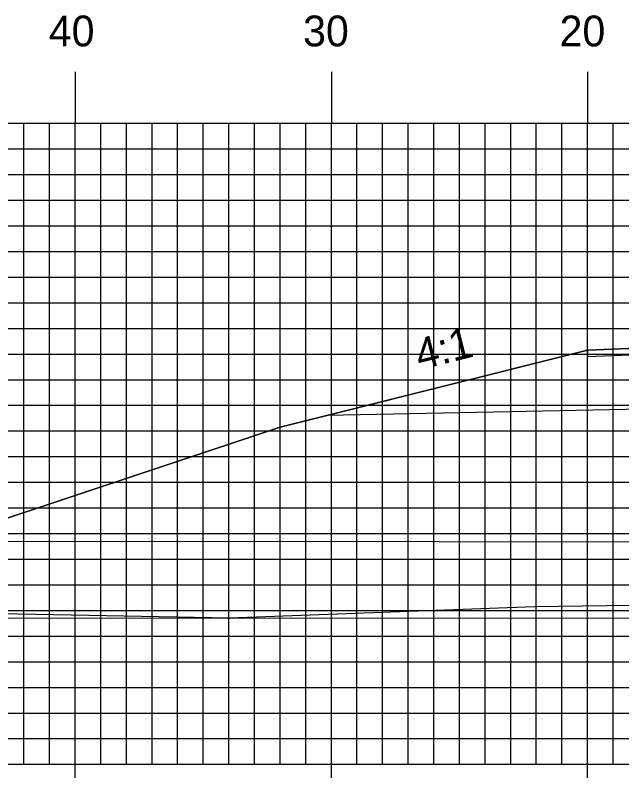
# Model space of a CAD drawing. Extents: x 1819244 to 1819587, y 442591 to 442811.
# Drawn here: x 1819367.32 to 1819391.01, y 442608.41 to 442637.88 of the extents above; entities that cross this region are included whole.
import ezdxf

# ---------------------------------------------------------------- set-up
doc = ezdxf.new("R2010")
doc.units = 0
for name, color, linetype in [('ANNOTATION', 7, 'Continuous'), ('D_Drainage_Culvert', 7, 'Continuous'), ('D_Roadway_Centerline', 7, 'Continuous'), ('D_Roadway_Edge_Shoulder', 7, 'Continuous'), ('D_Roadway_SlopeLines', 7, 'Continuous'), ('D_Roadway_SubGrade', 7, 'Continuous'), ('H_V ANNOTATION', 7, 'Continuous'), ('MAJOR', 7, 'Continuous'), ('MINOR', 7, 'Continuous'), ('S_Roadway_Centerline', 7, 'Continuous')]:
    doc.layers.add(name, color=color, linetype=linetype)

msp = doc.modelspace()

# ---------------------------------------------------------------- linework, layer by layer
at = {"layer": 'D_Drainage_Culvert'}
msp.add_lwpolyline([(1819357.867, 442614.363), (1819357.868, 442617.363), (1819461.868, 442617.321), (1819461.867, 442614.321)], close=True, dxfattribs=at)
at = {"layer": 'D_Roadway_Centerline'}
msp.add_lwpolyline([(1819366.978, 442618.255), (1819377.665, 442621.817), (1819379.491, 442622.273), (1819389.665, 442624.817), (1819397.665, 442625.137), (1819409.665, 442625.377), (1819421.665, 442625.137), (1819429.665, 442624.817), (1819439.839, 442622.273), (1819441.665, 442621.817), (1819452.46, 442618.218)], dxfattribs=at)
at = {"layer": 'D_Roadway_Edge_Shoulder'}
msp.add_lwpolyline([(1819397.665, 442625.137), (1819389.665, 442624.817), (1819389.665, 442624.567), (1819397.665, 442624.887)], close=True, dxfattribs=at)
at = {"layer": 'D_Roadway_SlopeLines'}
msp.add_lwpolyline([(1819389.665, 442624.817), (1819377.665, 442621.817), (1819366.978, 442618.255)], dxfattribs=at)
at = {"layer": 'D_Roadway_SubGrade'}
msp.add_lwpolyline([(1819397.665, 442622.637), (1819379.491, 442622.273), (1819389.665, 442624.817), (1819389.665, 442624.567), (1819397.665, 442624.887), (1819409.665, 442625.127), (1819421.665, 442624.887), (1819429.665, 442624.567), (1819429.665, 442624.817), (1819439.839, 442622.273), (1819421.665, 442622.637), (1819409.665, 442622.877)], close=True, dxfattribs=at)
at = {"layer": 'MAJOR'}
for p, q in [((1819369.665, 442635.669), (1819369.665, 442633.665)), ((1819379.665, 442635.669), (1819379.665, 442633.665)), ((1819389.665, 442635.669), (1819389.665, 442633.665)), ((1819269.665, 442633.665), (1819549.665, 442633.665)), ((1819269.665, 442633.665), (1819549.665, 442633.665)), ((1819369.665, 442608.665), (1819369.665, 442633.665)), ((1819379.665, 442608.665), (1819379.665, 442633.665)), ((1819389.665, 442608.665), (1819389.665, 442633.665)), ((1819269.665, 442628.665), (1819549.665, 442628.665)), ((1819269.665, 442623.665), (1819549.665, 442623.665)), ((1819269.665, 442618.665), (1819549.665, 442618.665)), ((1819269.665, 442613.665), (1819549.665, 442613.665)), ((1819269.665, 442608.665), (1819549.665, 442608.665)), ((1819269.665, 442608.665), (1819549.665, 442608.665)), ((1819369.665, 442606.661), (1819369.665, 442608.665)), ((1819379.665, 442606.661), (1819379.665, 442608.665)), ((1819389.665, 442606.661), (1819389.665, 442608.665))]:
    msp.add_line(p, q, dxfattribs=at)
at = {"layer": 'MINOR'}
for p, q in [((1819367.665, 442608.665), (1819367.665, 442633.665)), ((1819368.665, 442608.665), (1819368.665, 442633.665)), ((1819370.665, 442608.665), (1819370.665, 442633.665)), ((1819371.665, 442608.665), (1819371.665, 442633.665)), ((1819372.665, 442608.665), (1819372.665, 442633.665)), ((1819373.665, 442608.665), (1819373.665, 442633.665)), ((1819374.665, 442608.665), (1819374.665, 442633.665)), ((1819375.665, 442608.665), (1819375.665, 442633.665)), ((1819376.665, 442608.665), (1819376.665, 442633.665)), ((1819377.665, 442608.665), (1819377.665, 442633.665)), ((1819378.665, 442608.665), (1819378.665, 442633.665)), ((1819380.665, 442608.665), (1819380.665, 442633.665)), ((1819381.665, 442608.665), (1819381.665, 442633.665)), ((1819382.665, 442608.665), (1819382.665, 442633.665)), ((1819383.665, 442608.665), (1819383.665, 442633.665)), ((1819384.665, 442608.665), (1819384.665, 442633.665)), ((1819385.665, 442608.665), (1819385.665, 442633.665)), ((1819386.665, 442608.665), (1819386.665, 442633.665)), ((1819387.665, 442608.665), (1819387.665, 442633.665)), ((1819388.665, 442608.665), (1819388.665, 442633.665)), ((1819390.665, 442608.665), (1819390.665, 442633.665)), ((1819269.665, 442632.665), (1819549.665, 442632.665)), ((1819269.665, 442631.665), (1819549.665, 442631.665)), ((1819269.665, 442630.665), (1819549.665, 442630.665)), ((1819269.665, 442629.665), (1819549.665, 442629.665)), ((1819269.665, 442627.665), (1819549.665, 442627.665)), ((1819269.665, 442626.665), (1819549.665, 442626.665)), ((1819269.665, 442625.665), (1819549.665, 442625.665)), ((1819269.665, 442624.665), (1819549.665, 442624.665)), ((1819269.665, 442622.665), (1819549.665, 442622.665)), ((1819269.665, 442621.665), (1819549.665, 442621.665)), ((1819269.665, 442620.665), (1819549.665, 442620.665)), ((1819269.665, 442619.665), (1819549.665, 442619.665)), ((1819269.665, 442617.665), (1819549.665, 442617.665)), ((1819269.665, 442616.665), (1819549.665, 442616.665)), ((1819269.665, 442615.665), (1819549.665, 442615.665)), ((1819269.665, 442614.665), (1819549.665, 442614.665)), ((1819269.665, 442612.665), (1819549.665, 442612.665)), ((1819269.665, 442611.665), (1819549.665, 442611.665)), ((1819269.665, 442610.665), (1819549.665, 442610.665)), ((1819269.665, 442609.665), (1819549.665, 442609.665))]:
    msp.add_line(p, q, dxfattribs=at)
at = {"layer": 'S_Roadway_Centerline'}
msp.add_lwpolyline([(1819269.665, 442615.62), (1819293.864, 442614.517), (1819306.637, 442614.196), (1819311.939, 442614.111), (1819327.13, 442614.269), (1819335.506, 442614.454), (1819347.417, 442614.452), (1819360.584, 442614.34), (1819366.063, 442614.563), (1819375.686, 442614.381), (1819387.593, 442614.823), (1819390.429, 442614.853), (1819412.092, 442614.909), (1819428.463, 442614.6), (1819437.115, 442614.23), (1819454.085, 442614.332), (1819455.159, 442614.334), (1819459.077, 442614.335), (1819469.488, 442614.315), (1819471.654, 442614.398)], dxfattribs=at)

# ---------------------------------------------------------------- texts
at = {"layer": 'ANNOTATION'}
msp.add_text('4:1', height=1.2, rotation=14.0362, dxfattribs=at).set_placement((1819383.113, 442624.04))
at = {"layer": 'H_V ANNOTATION'}
for s, p in [('40', (1819368.637, 442636.665)), ('30', (1819378.562, 442636.665)), ('20', (1819388.573, 442636.665))]:
    msp.add_text(s, height=1.2, dxfattribs=at).set_placement(p)

doc.saveas('drawing.dxf')
